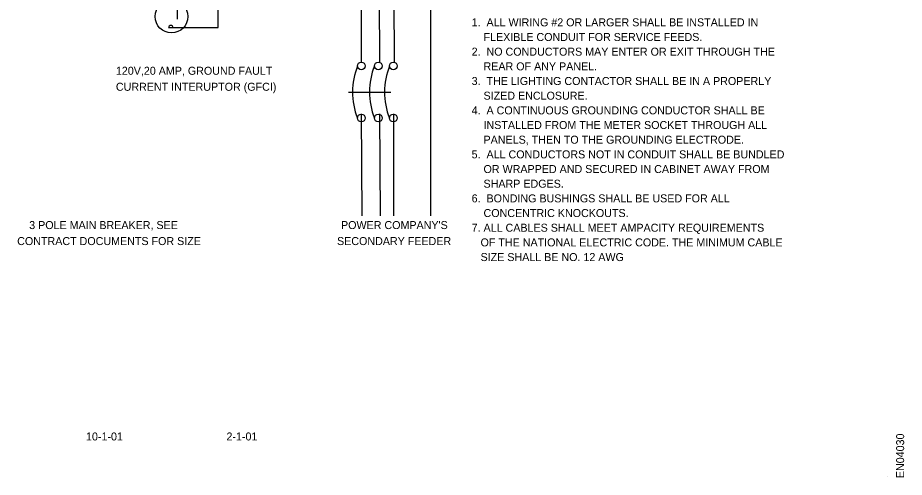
# Model space of a CAD drawing. Extents: x 10006.6 to 10036.5, y 10000 to 10010.3.
# Drawn here: x 10029.9 to 10036.55, y 10000.05 to 10003.49 of the extents above; entities that cross this region are included whole.
import ezdxf

# ---------------------------------------------------------------- set-up
doc = ezdxf.new("R2010")
doc.units = 0
for name, color, linetype in [('APPROVAL-OLD', 7, 'Continuous'), ('DETL-LINE', 7, 'Continuous'), ('DETL-NOTE', 7, 'Continuous'), ('EN', 7, 'Continuous'), ('TTLB-TEXT', 7, 'Continuous')]:
    doc.layers.add(name, color=color, linetype=linetype)

msp = doc.modelspace()

# ---------------------------------------------------------------- linework, layer by layer
at = {"layer": 'DETL-LINE'}
for p, q in [((10032.476, 10007.089), (10032.476, 10003.163)), ((10032.593, 10007.089), (10032.613, 10003.163)), ((10032.704, 10007.089), (10032.723, 10003.163)), ((10031.404, 10003.4196), (10031.404, 10003.702)), ((10031.095, 10003.586), (10031.095, 10003.484)), ((10032.379, 10002.935), (10032.697, 10002.935)), ((10032.476, 10002.773), (10032.479, 10002.008)), ((10032.613, 10002.773), (10032.617, 10002.008)), ((10032.717, 10002.773), (10032.717, 10002.008))]:
    msp.add_line(p, q, dxfattribs=at)
for centre, radius in [((10031.0533, 10003.5029), 0.123), ((10032.4764, 10003.1327), 0.0287), ((10032.6035, 10003.1327), 0.0287), ((10032.7161, 10003.1327), 0.0287), ((10032.4764, 10002.7418), 0.0287), ((10032.6035, 10002.7418), 0.0287), ((10032.7161, 10002.7418), 0.0287)]:
    msp.add_circle(centre, radius, dxfattribs=at)
for centre, radius, start, end in [((10031.048, 10003.4186), 0.0169, 5.3234, 175.10921), ((10032.9502, 10002.9357), 0.5398, 158.59419, 201.098), ((10033.0774, 10002.9357), 0.5398, 158.59419, 201.098), ((10033.19, 10002.9357), 0.5398, 158.59419, 201.098)]:
    msp.add_arc(centre, radius, start, end, dxfattribs=at)
at = {"layer": 'TTLB-TEXT'}
for p, q in [((10032.99, 10006.809), (10032.996, 10002.008)), ((10031.0314, 10003.4196), (10031.404, 10003.4196)), ((10036.4235, 10000.0515), (10036.4235, 10000.0515))]:
    msp.add_line(p, q, dxfattribs=at)

# ---------------------------------------------------------------- texts
at = {"layer": 'APPROVAL-OLD'}
for s, p in [('10-1-01', (10030.412, 10000.3239)), ('2-1-01', (10031.465, 10000.3239))]:
    msp.add_text(s, height=0.06, dxfattribs=at).set_placement(p)
at = {"layer": 'DETL-NOTE'}
for s, p in [('1.  ALL WIRING #2 OR LARGER SHALL BE INSTALLED IN', (10033.3032, 10003.4291)), ('    FLEXIBLE CONDUIT FOR SERVICE FEEDS.', (10033.3032, 10003.3191)), ('2.  NO CONDUCTORS MAY ENTER OR EXIT THROUGH THE', (10033.3032, 10003.2091)), ('    REAR OF ANY PANEL.', (10033.3032, 10003.0991)), ('120V,20 AMP, GROUND FAULT', (10030.636, 10003.066)), ('3.  THE LIGHTING CONTACTOR SHALL BE IN A PROPERLY', (10033.3032, 10002.9891)), ('CURRENT INTERUPTOR (GFCI)', (10030.636, 10002.946)), ('    SIZED ENCLOSURE.', (10033.3032, 10002.8791)), ('4.  A CONTINUOUS GROUNDING CONDUCTOR SHALL BE', (10033.3032, 10002.7691)), ('    INSTALLED FROM THE METER SOCKET THROUGH ALL', (10033.3032, 10002.6591)), ('    PANELS, THEN TO THE GROUNDING ELECTRODE.', (10033.3032, 10002.5491)), ('5.  ALL CONDUCTORS NOT IN CONDUIT SHALL BE BUNDLED', (10033.3032, 10002.4391)), ('    OR WRAPPED AND SECURED IN CABINET AWAY FROM', (10033.3032, 10002.3291)), ('    SHARP EDGES.', (10033.3032, 10002.2191)), ('6.  BONDING BUSHINGS SHALL BE USED FOR ALL', (10033.3032, 10002.1091)), ('    CONCENTRIC KNOCKOUTS.', (10033.3032, 10001.9991)), ('3 POLE MAIN BREAKER, SEE', (10029.986, 10001.909)), ("POWER COMPANY'S", (10032.324, 10001.909)), ('7. ALL CABLES SHALL MEET AMPACITY REQUIREMENTS', (10033.3032, 10001.8891)), ('CONTRACT DOCUMENTS FOR SIZE', (10029.896, 10001.789)), ('SECONDARY FEEDER', (10032.294, 10001.789)), ('   OF THE NATIONAL ELECTRIC CODE. THE MINIMUM CABLE', (10033.3032, 10001.7791)), ('   SIZE SHALL BE NO. 12 AWG', (10033.3032, 10001.6691))]:
    msp.add_text(s, height=0.06, dxfattribs=at).set_placement(p)
at = {"layer": 'EN'}
msp.add_text('EN04030', height=0.06, rotation=90, dxfattribs=at).set_placement((10036.546, 10000.0414))

doc.saveas('drawing.dxf')
